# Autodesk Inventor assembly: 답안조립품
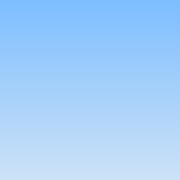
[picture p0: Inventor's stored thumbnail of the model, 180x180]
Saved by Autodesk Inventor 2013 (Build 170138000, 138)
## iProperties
Created: 2016-09
Part Number: 답안조립품
Document SubType Name: Assembly
Designer: Administrator
Author: Administrator
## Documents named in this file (1)
- C:\Users\Administrator\Desktop\460907V1015\답안조립품.iam
